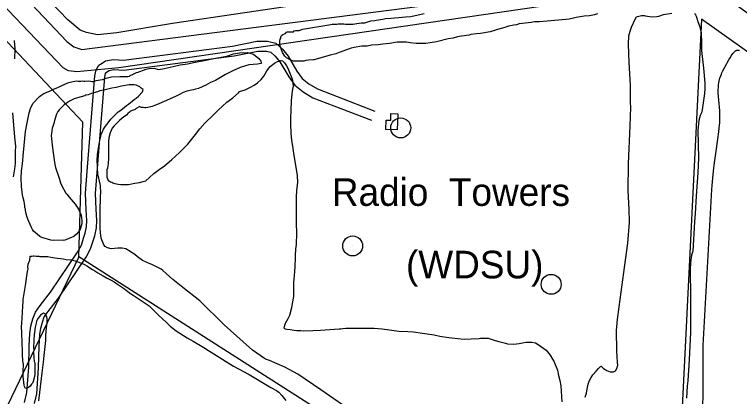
# Model space of a CAD drawing. Extents: x 3683402 to 3721514, y 487807 to 513565.
# Drawn here: x 3700574 to 3702752, y 509434 to 510583 of the extents above; entities that cross this region are included whole.
import ezdxf

# ---------------------------------------------------------------- set-up
doc = ezdxf.new("R2010")
doc.units = 0
for name, color, linetype in [('V-BLDG-OTLN', 7, 'Continuous'), ('V-LEVE-TOET', 7, 'Continuous'), ('V-ROAD-CNTR', 7, 'Continuous'), ('V-SITE-VEGE', 7, 'Continuous'), ('V-TOPO-BNDY', 7, 'Continuous'), ('V-TOPO-SHOR', 7, 'Continuous'), ('V-TOPO-TOWR', 7, 'Continuous'), ('V-TOPO-TOWR-IDEN', 7, 'Continuous')]:
    doc.layers.add(name, color=color, linetype=linetype)

msp = doc.modelspace()

# ---------------------------------------------------------------- linework, layer by layer
at = {"layer": 'V-BLDG-OTLN'}
msp.add_lwpolyline([(3701724, 510236.5), (3701689.8, 510237.3), (3701690.4, 510265.1), (3701704.2, 510264.8), (3701704.7, 510285.1), (3701725.2, 510284.6)], close=True, dxfattribs=at)
at = {"layer": 'V-LEVE-TOET'}
for points in [[(3703957.8, 509729.9), (3702683.1, 510654.5), (3702663.2, 510664.5), (3702627.6, 510671.7), (3702562.1, 510667), (3700887.3, 510422.1), (3700761.2, 510410.4), (3700735.6, 510413.3), (3700720, 510422.6), (3699648.8, 511545.4)], [(3699737, 511546.5), (3700239, 511021.5), (3700730.9, 510501.6), (3700752.2, 510485.2), (3700775.7, 510477.3), (3702629.2, 510715.9), (3702662.7, 510717.9), (3702689.7, 510707.2), (3702727.4, 510684.3), (3703765.4, 509932.7), (3703987.1, 509768.3)]]:
    msp.add_lwpolyline(points, dxfattribs=at)
at = {"layer": 'V-ROAD-CNTR'}
for points in [[(3700793.4, 510123.6), (3700802.4, 510236), (3700815.5, 510398.7), (3700818.7, 510416.9), (3700827.1, 510430.3), (3700837.3, 510436.9), (3700847.3, 510443.1), (3700870.8, 510447.5), (3700901.7, 510445.4), (3701228.8, 510487.9), (3701301.7, 510502.3), (3701334, 510502.8), (3701359, 510496.8), (3701379, 510478.3), (3701395.5, 510457.3), (3701422.5, 510412), (3701438.3, 510390.8), (3701458, 510374.6), (3701483.8, 510359.2), (3701543.7, 510336), (3701656.6, 510292.7)], [(3700823.3, 510121.2), (3700832.3, 510233.6), (3700845.3, 510394.9), (3700847.3, 510405.9), (3700849, 510408.8), (3700853.3, 510411.5), (3700858.3, 510414.6), (3700872.6, 510417.3), (3700902.6, 510415.3), (3701233.6, 510458.3), (3701304.9, 510472.3), (3701330.7, 510472.7), (3701344.4, 510469.4), (3701356.9, 510457.8), (3701370.7, 510440.3), (3701397.5, 510395.3), (3701416.5, 510369.9), (3701440.6, 510350), (3701470.6, 510332.1), (3701532.9, 510308), (3701645.9, 510264.7)], [(3700604.2, 509416.8), (3700610.7, 509446.6), (3700616.3, 509522.5), (3700617.7, 509587.2), (3700620.1, 509623.5), (3700623, 509645.5), (3700628.8, 509667.5), (3700636.4, 509687.9), (3700650.8, 509707.7), (3700681.8, 509747.7), (3700763.2, 509868.4), (3700774.6, 509889.8), (3700781.5, 509910.9), (3700785.7, 509925.1), (3700789.7, 509945), (3700790.8, 509963.6), (3700788.7, 509995.6), (3700786.6, 510045.5), (3700790.3, 510084.8), (3700793.4, 510123.6)], [(3700634.1, 509413.1), (3700640.5, 509442.2), (3700646.3, 509521.1), (3700647.7, 509585.9), (3700650, 509620.6), (3700652.4, 509639.7), (3700657.4, 509658.4), (3700663.1, 509673.6), (3700674.8, 509689.7), (3700706.1, 509730.1), (3700788.9, 509853), (3700802.3, 509878), (3700810.2, 509902), (3700814.8, 509917.9), (3700819.6, 509941.1), (3700820.9, 509963.7), (3700818.7, 509997.3), (3700816.7, 510044.7), (3700820.2, 510082.3), (3700823.3, 510121.2)]]:
    msp.add_lwpolyline(points, dxfattribs=at)
at = {"layer": 'V-SITE-VEGE'}
for points in [[(3702325.2, 510584.7), (3702316, 510582.2), (3702301.1, 510579), (3702285.3, 510578.2), (3702279.5, 510576.5), (3702261.2, 510573.3), (3702253.7, 510571.6), (3702240.4, 510568.4), (3702230.4, 510567.5), (3702173.9, 510562.7), (3702151.5, 510561.1), (3702135.7, 510560.4), (3702125.7, 510558.7), (3702117.4, 510557.9), (3702090, 510554.7), (3702082.5, 510551.4), (3702074.2, 510550.6), (3702057.6, 510547.3), (3702051.7, 510545.7), (3702046.7, 510544), (3702025.1, 510537.4), (3702016, 510535), (3702002.7, 510530.9), (3701974.4, 510526), (3701961.9, 510524.3), (3701945.3, 510522.7), (3701939.5, 510521.1), (3701917.1, 510517.8), (3701904.6, 510515.4), (3701891.3, 510512.1), (3701877.2, 510509.6), (3701841.4, 510500.6), (3701822.3, 510497.3), (3701809.8, 510495.7), (3701780.7, 510495.8), (3701763.3, 510497.5), (3701751.7, 510500), (3701745.9, 510500.1), (3701723.4, 510499.3), (3701700.2, 510496), (3701680.2, 510493.6), (3701666.1, 510492), (3701646.1, 510490.4), (3701633.7, 510487.9), (3701617, 510487.2), (3701593.8, 510483.9), (3701585.5, 510481.4), (3701549.7, 510468.3), (3701539.7, 510465), (3701522.2, 510460.9), (3701498.1, 510453.5), (3701487.3, 510451), (3701474, 510446.9), (3701471.5, 510446.9), (3701457.4, 510445.3), (3701449.1, 510444.5), (3701443.3, 510442.8), (3701425.8, 510442.9), (3701418.3, 510442.1), (3701411.7, 510442.9), (3701404.2, 510445.4), (3701400.1, 510447.1), (3701395.1, 510450.5), (3701391, 510453), (3701386, 510458), (3701379.4, 510468.8), (3701372.8, 510484.6), (3701371.1, 510492.1), (3701371.2, 510502.9), (3701372, 510508.7), (3701373.7, 510512), (3701373.7, 510515.3), (3701376.2, 510519.5), (3701379.5, 510522.8), (3701384.5, 510524.4), (3701387.9, 510526.1), (3701391.2, 510529.4), (3701393.7, 510531), (3701412, 510531), (3701414.5, 510533.5), (3701417.8, 510534.3), (3701423.6, 510534.3), (3701429.4, 510535.1), (3701436.9, 510537.6), (3701439.4, 510539.2)], [(3701439.4, 510539.2), (3701524.2, 510553.1), (3701528.3, 510553.9), (3701542.5, 510553.9), (3701545.8, 510554.7), (3701558.3, 510554.6), (3701563.2, 510554.6), (3701568.2, 510553.8), (3701589.8, 510553.7), (3701596.5, 510554.5), (3701615.6, 510557.8), (3701626.4, 510557.8), (3701638, 510561.9), (3701644.7, 510563.5), (3701656.3, 510565.1), (3701660.5, 510566), (3701680.4, 510569.2), (3701688.7, 510570.9), (3701704.5, 510571.6), (3701738.6, 510574.9), (3701748.6, 510575.7), (3701764.4, 510577.3), (3701805.1, 510585.5)], [(3702490.1, 510576), (3702503.4, 510577.1), (3702509.7, 510578.2), (3702523.6, 510582.8), (3702549, 510587.3)], [(3702616.6, 510586), (3702620, 510581.9), (3702622.3, 510577.9), (3702628.1, 510558.8), (3702632.6, 510546.1), (3702634.3, 510540.9), (3702637.2, 510528.2), (3702637.2, 510520.7), (3702638.3, 510503.3), (3702638.2, 510488.9), (3702637.6, 510475), (3702643.8, 510421.3), (3702647.7, 510376.3), (3702647.7, 510360.7), (3702646.5, 510345.7), (3702640, 510296.6), (3702638.2, 510286.8), (3702633.6, 510278.7), (3702630, 510264.3), (3702627.1, 510233.7), (3702628.5, 510150.5), (3702627.3, 510107.8), (3702622.4, 510036.2), (3702619.4, 509984.8), (3702617, 509960)], [(3702287.9, 509432), (3702292, 509444.7), (3702293.8, 509451.6), (3702297.9, 509471.2), (3702300.8, 509480.5), (3702306.6, 509492), (3702311.8, 509499.5), (3702321.1, 509510.4), (3702328.6, 509519.1), (3702335.6, 509526), (3702337.9, 509524.8), (3702343.7, 509519), (3702353.5, 509512.6), (3702363.3, 509508.6), (3702370.2, 509509.1), (3702373.7, 509509.1), (3702380, 509512), (3702383.5, 509518.9), (3702385.8, 509525.3), (3702386.4, 509528.1), (3702385.9, 509538.5), (3702384.8, 509553), (3702383.1, 509572), (3702382.1, 509633.3), (3702385.1, 509665.6), (3702390.4, 509703.7), (3702396.9, 509748.1), (3702409.3, 509844), (3702416.4, 509895.9), (3702421.8, 509957.7), (3702421.8, 509972.7), (3702420.7, 509984.3), (3702420.2, 509996.4), (3702418, 510054.1), (3702417.6, 510085.3), (3702418.8, 510102.1), (3702418.3, 510133.8), (3702423.3, 510248.2), (3702425.1, 510275.9), (3702425.2, 510304.7), (3702424.6, 510318.6), (3702424.2, 510370.6), (3702420.4, 510438.2), (3702418.2, 510493.6), (3702420, 510519), (3702423.5, 510532.9), (3702427.6, 510544.4), (3702440.4, 510572.7), (3702441.6, 510574.4), (3702445.6, 510577.3), (3702457.2, 510580.1), (3702461.2, 510580.1), (3702466.4, 510579.5), (3702468.7, 510578.9), (3702490.1, 510576)], [(3700572.3, 510504.5), (3700574.9, 510479.2), (3700573.5, 510449.8)], [(3702688.9, 510364.2), (3702689.5, 510371.2), (3702690.4, 510377.2), (3702691.3, 510382.6), (3702692.3, 510387.2), (3702693.4, 510391.3), (3702695.6, 510398.4), (3702697.6, 510403.8), (3702699.3, 510407.8), (3702702.2, 510413.8), (3702708.1, 510424.3), (3702721.2, 510448.1), (3702724.6, 510453.8), (3702727.5, 510458.6), (3702730.1, 510462.4), (3702732.4, 510465.5), (3702734.3, 510467.9), (3702736.1, 510469.8), (3702738.9, 510472.4), (3702741.2, 510474.1), (3702743, 510475), (3702744.3, 510475.5), (3702746.2, 510475.9), (3702748.2, 510475.9), (3702749.6, 510475.7), (3702750.9, 510475.3), (3702752.2, 510474.7)], [(3701172.4, 510450.6), (3701183.4, 510452.3), (3701211.2, 510458), (3701231.4, 510464.3), (3701249.3, 510467.1), (3701273.6, 510468.8), (3701287.4, 510464.7), (3701292, 510463.5), (3701308.2, 510450.8), (3701313.9, 510442.1), (3701315, 510438.6), (3701315, 510435.7), (3701304.1, 510433.5), (3701278.1, 510431.8), (3701252.1, 510423.8), (3701229.5, 510413.5), (3701208.1, 510402), (3701177.4, 510384.8), (3701163, 510377.9), (3701148.5, 510370.4), (3701141.6, 510367), (3701137.5, 510365.3), (3701126.5, 510360.1), (3701117.9, 510358.4), (3701110.9, 510356.1), (3701091.3, 510352.7), (3701080.9, 510348.1), (3701069.3, 510342.4), (3701057.2, 510336), (3701023.6, 510321.1), (3701016.1, 510318.3), (3701005.7, 510313.1), (3700992.4, 510307.9), (3700987.2, 510306.2), (3700974.5, 510303.4), (3700968.7, 510302.2), (3700965.8, 510302.3), (3700960.1, 510302.8), (3700957.7, 510303.4), (3700954.9, 510303.4), (3700952, 510304), (3700950.2, 510306.3), (3700947.9, 510305.2), (3700941.6, 510301.2), (3700939.3, 510300.6), (3700935.8, 510297.7), (3700930, 510294.9), (3700922.5, 510292), (3700919.6, 510289.1), (3700914.4, 510285.1), (3700910.9, 510281.6), (3700901.1, 510274.1), (3700897, 510271.3), (3700889.5, 510263.8), (3700880.2, 510255.2), (3700873.3, 510247.7), (3700867.5, 510240.8), (3700861.1, 510226.9), (3700857.6, 510212.5), (3700856.4, 510201.5), (3700856.2, 510146.1), (3700855.6, 510140.3), (3700855, 510136.8), (3700855, 510132.8), (3700854.4, 510128.8), (3700852.7, 510121.3), (3700851.5, 510115.5), (3700851.4, 510094.7), (3700852, 510091.8), (3700853.7, 510086), (3700856, 510083.1), (3700858.9, 510082), (3700862.4, 510080.2), (3700865.8, 510079.1), (3700869.3, 510076.7), (3700875.6, 510074.4), (3700885.4, 510072.7), (3700893.5, 510072.1), (3700896.4, 510072), (3700916, 510071.4), (3700935.7, 510075.4), (3700949, 510078.2), (3700960.5, 510080.5), (3700968.6, 510082.8), (3700979.1, 510093.2), (3700992.4, 510104.7), (3701008, 510116.7), (3701024.2, 510128.2), (3701046.8, 510147.2), (3701068.8, 510167.4), (3701094.9, 510193.3), (3701118, 510222.1), (3701130.8, 510239.4), (3701145.9, 510256.1), (3701171.4, 510280.8), (3701185.8, 510295.2), (3701211.9, 510318.8), (3701229.8, 510332.6), (3701246.6, 510347.6), (3701249.5, 510351.6), (3701266.3, 510356.8)], [(3700738.1, 510033.8), (3700755.9, 510012.4), (3700763.9, 510000.8), (3700766.2, 509997.9), (3700774.3, 509979.4), (3700776.5, 509963.8), (3700776.5, 509954), (3700770.1, 509934.4), (3700760.2, 509922.9), (3700752.1, 509915.4), (3700723.2, 509903.9), (3700719.8, 509904), (3700691.5, 509903.5), (3700682.8, 509904.6), (3700655.7, 509912.8), (3700649.9, 509915.7), (3700641.3, 509922.1), (3700630.3, 509931.9), (3700627.5, 509936.6), (3700623.4, 509944.1), (3700613.7, 509967.8), (3700612.6, 509970.1), (3700610.8, 509976.5), (3700608, 509988), (3700606.8, 509994.4), (3700606.3, 509997.3), (3700605.7, 509999.6), (3700604.6, 510001.3), (3700604.6, 510007.7), (3700603.4, 510014.6), (3700602.3, 510020.4), (3700599.5, 510031.9), (3700597.8, 510041.2), (3700594.4, 510066), (3700593.9, 510092), (3700595.1, 510112.2), (3700597.5, 510133.6), (3700600.4, 510168.2), (3700607, 510231.2), (3700612.3, 510261.7), (3700618.1, 510287.1), (3700622.2, 510299.8), (3700628.6, 510315.4), (3700648.9, 510336.7), (3700652.9, 510339.6), (3700662.2, 510345.3), (3700664.5, 510346.5), (3700670.9, 510349.3), (3700676.7, 510351.6), (3700685.3, 510355.7), (3700688.8, 510357.4), (3700706.1, 510364.8), (3700716, 510369.4), (3700731.6, 510376.3), (3700736.8, 510378), (3700759.3, 510383.1), (3700765.1, 510382.6), (3700767.4, 510382.5), (3700772.6, 510382.5), (3700777.8, 510383.1), (3700782.4, 510382.5), (3700784.7, 510382.5), (3700795.1, 510383), (3700802.1, 510382.4), (3700806.7, 510381.9), (3700809, 510381.8), (3700814.2, 510382.4), (3700819.4, 510384.1), (3700825.2, 510385.3), (3700838.5, 510387.5), (3700840.8, 510388.1), (3700848.9, 510391), (3700853.5, 510392.1), (3700865.1, 510395.5), (3700889.9, 510396), (3700914.1, 510396), (3700918.8, 510397.7), (3700921.1, 510399.4), (3700922.8, 510400.6), (3700928, 510402.9), (3700930.9, 510404.6), (3700934.4, 510405.7), (3700938.4, 510407.4), (3700940.2, 510408.6), (3700944.8, 510409.7), (3700947.1, 510410.9), (3700950.6, 510411.4), (3700952.9, 510412.6), (3700958.7, 510414.3), (3700961, 510415.5), (3700969.6, 510418.3), (3700977.7, 510420.6), (3700992.2, 510421.7), (3701007.2, 510417), (3701023.9, 510420.5), (3701050.5, 510426.2), (3701071.3, 510431.3), (3701093.9, 510434.1), (3701117, 510439.2), (3701138.9, 510443.2), (3701172.4, 510450.6)], [(3701266.3, 510356.8), (3701283.1, 510364.2), (3701294.1, 510370), (3701303.9, 510376.9), (3701314.9, 510387.2), (3701322.4, 510397), (3701327.1, 510404.5), (3701331.7, 510413.7), (3701341.6, 510426.4), (3701354.9, 510436.2), (3701364.1, 510441.4), (3701375.1, 510444.2), (3701379.2, 510443.6), (3701384.9, 510437.3), (3701390.7, 510428), (3701394.7, 510421.1), (3701401, 510406), (3701404.4, 510399.1), (3701407.9, 510388.1), (3701409, 510385.2), (3701411.3, 510367.3), (3701409.5, 510358.1), (3701407.2, 510344.8), (3701405.4, 510322.9), (3701405.3, 510313.6), (3701404.2, 510303.8), (3701404.1, 510293.4), (3701402.9, 510273.2), (3701402.8, 510253.6), (3701403.9, 510226.4), (3701405.6, 510203.9), (3701409, 510187.1), (3701411.8, 510166.3), (3701423.2, 510099.3), (3701423.7, 510077.4), (3701421.3, 510054.9), (3701420.1, 510034.1), (3701420, 509997.7), (3701420.5, 509994.8), (3701420.4, 509955.5), (3701421.5, 509925.5), (3701420.2, 509891.4), (3701418.4, 509877), (3701417.2, 509857.9), (3701417.2, 509851), (3701416, 509825.6), (3701415.4, 509810.6), (3701413, 509786.3), (3701412.4, 509778.8), (3701412.3, 509749.4), (3701411.7, 509735.5), (3701407.6, 509714.2), (3701405.8, 509701.5), (3701399.9, 509677.8), (3701395.3, 509668), (3701387.2, 509654.2), (3701383.1, 509640.9), (3701384.8, 509639.2), (3701387.1, 509637.4), (3701392.3, 509636.8), (3701402.1, 509636.2), (3701413.7, 509633.9), (3701422.3, 509633.3), (3701434.5, 509633.2), (3701443.1, 509632.1), (3701469.7, 509633.1), (3701493.4, 509634.2), (3701549.4, 509638.1), (3701554, 509638.1), (3701559.8, 509638.6), (3701569, 509639.8), (3701654.5, 509639.5), (3701678.7, 509637.7), (3701700.1, 509635.3), (3701728.4, 509630.6), (3701755.5, 509630), (3701772.3, 509628.8), (3701799.4, 509624.6), (3701834.6, 509619.9), (3701851.3, 509615.8), (3701878.5, 509611.7), (3701887.1, 509610.5), (3701925.2, 509606.9), (3701946, 509607.4), (3701969.7, 509609.1), (3701974.3, 509609.7), (3701996.9, 509609.6), (3702018.2, 509603.2), (3702029.2, 509599.7), (3702048.8, 509594.4), (3702055.1, 509593.2), (3702073.6, 509591.5), (3702090.4, 509593.7), (3702100.2, 509595.4), (3702111.2, 509598.3), (3702127.9, 509598.2), (3702139.5, 509595.3), (3702147.5, 509591.2), (3702171.1, 509573.3), (3702183.2, 509558.8), (3702190.7, 509546.6)], [(3701079.1, 509762.5), (3701049.2, 509785.7), (3701019.2, 509813), (3701014.6, 509817), (3701000.2, 509824), (3700988.6, 509829.8), (3700976.5, 509835), (3700958.7, 509843.7), (3700943.1, 509854.8), (3700935.6, 509861.7), (3700907.9, 509878.5), (3700897, 509880.3), (3700884.3, 509880.4), (3700864.6, 509878.1), (3700853.1, 509881.6), (3700846.2, 509885.7), (3700842.1, 509890.3), (3700834.1, 509910.5), (3700831.9, 509927.9), (3700830.7, 509939.4), (3700830.8, 509968.3), (3700831.5, 509986.8), (3700831.5, 509993.7), (3700832.2, 510032.4), (3700832.8, 510051.4), (3700832.3, 510061.8), (3700831.7, 510068.8), (3700828.9, 510082.1), (3700827.7, 510086.7), (3700827.2, 510090.7), (3700824.3, 510104), (3700823.8, 510108.6), (3700823.2, 510115.6), (3700823.2, 510130), (3700822.1, 510139.8), (3700822.1, 510142.7), (3700822.8, 510162.9), (3700825.1, 510174.5), (3700826.9, 510186.6), (3700830.4, 510203.9), (3700832.7, 510216), (3700834.5, 510223.5), (3700836.2, 510226.4), (3700840.9, 510238), (3700846.7, 510247.2), (3700850.8, 510252.4), (3700858.3, 510261.6), (3700862.9, 510267.9), (3700869.9, 510274.8), (3700875.1, 510280.6), (3700884.9, 510289.8), (3700893, 510295.5), (3700904, 510304.2), (3700910.4, 510308.8), (3700916.2, 510312.8), (3700933, 510327.2), (3700938.8, 510331.8), (3700946.3, 510337.5), (3700957.9, 510350.2), (3700960.2, 510357.1), (3700954.5, 510361.8), (3700949.9, 510365.8), (3700939.5, 510370.5), (3700933.1, 510371.6), (3700918.1, 510371.7), (3700895, 510367.1), (3700878.8, 510363.7), (3700866.1, 510361.5), (3700842.4, 510355.2), (3700830.3, 510352.9), (3700823.3, 510350), (3700804.8, 510344.9), (3700795, 510341.5), (3700788.1, 510340.3), (3700785.2, 510338.6), (3700763.2, 510332.3), (3700760.3, 510331.7), (3700752.8, 510329.5), (3700738.9, 510322), (3700733.1, 510318), (3700722.7, 510311.1), (3700708.2, 510296.1), (3700704.2, 510291.5), (3700700.1, 510283.4), (3700693.7, 510263.8), (3700691.4, 510255.2), (3700688.5, 510245.9), (3700687.3, 510241.3), (3700684.4, 510225.1), (3700684.3, 510218.8), (3700684.9, 510209), (3700688.3, 510181.8), (3700690, 510167.4), (3700694.5, 510132.1), (3700696.8, 510122.9), (3700707.6, 510090.5), (3700712.2, 510077.2), (3700715.1, 510069.7), (3700728.3, 510046), (3700730.6, 510042.5), (3700738.1, 510033.8)], [(3702642.4, 509393.3), (3702642.5, 509451.4), (3702642.6, 509509.4), (3702643, 509587.9), (3702669.4, 510056.6), (3702670.2, 510068.8), (3702671.1, 510080.2), (3702673.1, 510101.7), (3702675.2, 510120.4), (3702677.3, 510136.7), (3702681.1, 510165.3), (3702687.1, 510208.2), (3702689.9, 510229.6), (3702692.5, 510251.1), (3702693, 510256.3), (3702693.3, 510261.4), (3702693.5, 510266.4), (3702693.5, 510275.9), (3702693.1, 510284.9), (3702692.6, 510293.3), (3702689.8, 510324.9), (3702688.9, 510336.8), (3702688.5, 510347.2), (3702688.5, 510356.3), (3702688.9, 510364.2)], [(3700567.6, 510287), (3700574.1, 510213.6), (3700576.7, 510186.9), (3700575.3, 510170.9), (3700575.2, 510134.9), (3700573.8, 510118.9), (3700569.7, 510094.9)], [(3702617, 509960), (3702611.5, 509871.6), (3702608, 509859.5), (3702605.1, 509837), (3702603.8, 509816.2), (3702604.8, 509733.6), (3702604.6, 509683.4), (3702605, 509627.4), (3702601.3, 509544.8), (3702597.1, 509483), (3702595.9, 509472.6), (3702594.7, 509466.3), (3702592.9, 509429.3)], [(3700649.7, 509446.8), (3700656.8, 509505.7), (3700660.9, 509538), (3700663.3, 509557.6), (3700667.5, 509603.2), (3700668.1, 509618.3), (3700669.3, 509631), (3700672.2, 509656.9), (3700671.7, 509669.1), (3700670.6, 509674.3), (3700668.3, 509678.9), (3700666, 509682.9), (3700661.3, 509684.7), (3700652.1, 509678.9), (3700645.1, 509670.3), (3700641.1, 509663.4), (3700639.9, 509660.5), (3700638.7, 509654.7), (3700635.8, 509642.6), (3700634.6, 509635.7), (3700633.4, 509625.3), (3700632.9, 509621.8), (3700631, 509582), (3700631.6, 509573.3), (3700631, 509568.7), (3700632.1, 509551.4), (3700633.2, 509539.2), (3700634.3, 509535.2), (3700634.3, 509524.2), (3700634.9, 509516.7), (3700634.8, 509501.7), (3700634.2, 509494.8), (3700630.1, 509479.2), (3700627.8, 509474.6), (3700624.9, 509471.1), (3700620.3, 509465.9), (3700615.6, 509461.3), (3700613.3, 509460.2), (3700606.4, 509458.5), (3700603.5, 509464.3), (3700602.4, 509468.3), (3700599.6, 509494.9), (3700600.2, 509514.5), (3700600.8, 509526.6), (3700600.8, 509531.3), (3700599.1, 509540.5), (3700598, 509561.9), (3700597.5, 509576.9), (3700597, 509588.4), (3700596.4, 509604.6), (3700595.3, 509616.2), (3700595.3, 509627.1), (3700594.8, 509643.9), (3700596, 509655.4), (3700597.8, 509686.6), (3700598.5, 509706.8), (3700599.7, 509720.1), (3700599.7, 509726.5), (3700602.6, 509744.3), (3700606.1, 509762.2), (3700607.3, 509774.4), (3700609.7, 509788.8), (3700610.9, 509797.4), (3700613.2, 509810.1), (3700614.4, 509818.2), (3700613.8, 509822.8), (3700614.4, 509832.1), (3700619.7, 509844.2), (3700620.9, 509856.3), (3700626.1, 509856.3), (3700630.1, 509857.4), (3700632.4, 509856.9), (3700638.8, 509856.8), (3700643.4, 509856.3), (3700646.9, 509856.2), (3700650.3, 509855.7), (3700660.1, 509855), (3700673.4, 509855), (3700683.2, 509853.2), (3700689, 509852.1), (3700694.8, 509851.5), (3700719.6, 509848.5), (3700729.4, 509846.8), (3700745, 509845), (3700756, 509842), (3700780.2, 509833.3), (3700783.6, 509831.6), (3700791.1, 509826.9), (3700808.4, 509816.5), (3700815.3, 509811.8), (3700824, 509806.6), (3700840.1, 509797.3), (3700850.5, 509791.5), (3700864.3, 509784), (3700873.6, 509778.7), (3700877.6, 509775.8), (3700904.1, 509757.9), (3700914.5, 509750.3), (3700922.6, 509743.9), (3700930, 509738.7), (3700978.5, 509707.4)], [(3701634.6, 509357.2), (3701494, 509454.6), (3701424.8, 509501.6), (3701385.6, 509523.1), (3701339.5, 509542.9), (3701327.9, 509546.4), (3701288.7, 509574.2), (3701242.1, 509615.9), (3701204.1, 509649.5), (3701130.4, 509722.5), (3701079.1, 509762.5)], [(3700978.5, 509707.4), (3701006.7, 509679), (3701030.3, 509657), (3701041.2, 509646), (3701059.1, 509631.5), (3701092.5, 509611.2), (3701110.4, 509601.3), (3701142.7, 509581.6), (3701156.5, 509572.3), (3701231.4, 509525.9), (3701278.7, 509500.3), (3701343.8, 509462), (3701361.1, 509452.1), (3701367.5, 509447.5), (3701377.3, 509437.7), (3701388.8, 509422.6)], [(3702190.7, 509546.6), (3702194.1, 509540.9), (3702205, 509513.7), (3702208.5, 509497.5), (3702212.5, 509482.5), (3702215.3, 509466.9), (3702218.6, 509418.9)], [(3700647.3, 509421.4), (3700649.7, 509446.8)]]:
    msp.add_lwpolyline(points, dxfattribs=at)
at = {"layer": 'V-TOPO-BNDY'}
for p, q in [((3700778.7, 510259.1), (3699569.5, 511544.5)), ((3702638.3, 510568.9), (3702546.3, 508718)), ((3703283.1, 510108.1), (3702638.3, 510568.9)), ((3700766.6, 509854.3), (3700778.7, 510259.1)), ((3700766.6, 509854.3), (3699832.7, 507901.8)), ((3701607.5, 509317.4), (3700766.6, 509854.3))]:
    msp.add_line(p, q, dxfattribs=at)
at = {"layer": 'V-TOPO-SHOR'}
msp.add_lwpolyline([(3702956.1, 510641.5), (3702800.5, 510755.9), (3702759.3, 510776), (3702734.4, 510781.8), (3702697.3, 510784), (3702560.6, 510779.4), (3702257.8, 510734.1), (3701482.8, 510619.6), (3701048.2, 510555.5), (3700881.5, 510528.2), (3700823.1, 510522), (3700790.4, 510528.5), (3700771.1, 510535.7), (3700734.2, 510567.1), (3700147.2, 511177), (3699801.6, 511547.2)], dxfattribs=at)
at = {"layer": 'V-TOPO-TOWR'}
for p, q in [((3701734.2, 510241.9), (3701734.2, 510241.9)), ((3701589.8, 509887.1), (3701589.8, 509887.1)), ((3702186.2, 509771.6), (3702186.2, 509771.6))]:
    msp.add_line(p, q, dxfattribs=at)
for centre in [(3701734.2, 510241.9), (3701589.8, 509887.1), (3702186.2, 509771.6)]:
    msp.add_circle(centre, 30, dxfattribs=at)

# ---------------------------------------------------------------- texts
at = {"layer": 'V-TOPO-TOWR-IDEN'}
for s, p in [('Radio  Towers', (3701527.3, 510007.5)), ('(WDSU)', (3701750, 509789.6))]:
    msp.add_text(s, height=83, dxfattribs=at).set_placement(p)

doc.saveas('drawing.dxf')
